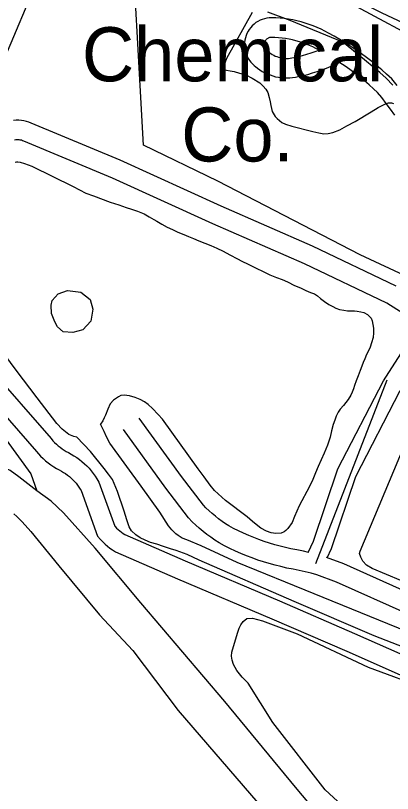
# Model space of a CAD drawing. Extents: x 3683613 to 3738215, y 469626 to 495384.
# Drawn here: x 3698541 to 3699120, y 478222 to 479415 of the extents above; entities that cross this region are included whole.
import ezdxf

# ---------------------------------------------------------------- set-up
doc = ezdxf.new("R2010")
doc.units = 0
for name, color, linetype in [('V-BLDG-IDEN', 7, 'Continuous'), ('V-ROAD-CNTR', 7, 'Continuous'), ('V-SITE-VEGE', 7, 'Continuous'), ('V-TOPO-SHOR', 7, 'Continuous')]:
    doc.layers.add(name, color=color, linetype=linetype)

msp = doc.modelspace()

# ---------------------------------------------------------------- linework, layer by layer
at = {"layer": 'V-ROAD-CNTR'}
for points in [[(3699021.9, 479388.6), (3699016.3, 479391.6), (3699010.5, 479394.5), (3699004.5, 479397.2), (3698998.4, 479399.6), (3698992.3, 479401.9), (3698986.1, 479403.9), (3698979.8, 479405.7), (3698973.4, 479407.3), (3698967, 479408.6), (3698960.6, 479409.8), (3698954.1, 479410.7), (3698947.6, 479411.3), (3698941.1, 479411.7), (3698934.3, 479411.9), (3698930.7, 479411.8), (3698927.2, 479411.3), (3698923.6, 479410.5), (3698920.2, 479409.5), (3698916.8, 479408.1), (3698913.6, 479406.4), (3698910.6, 479404.5), (3698907.7, 479402.2), (3698905, 479399.8), (3698902.6, 479397.1), (3698900.4, 479394.2), (3698898.4, 479391.2), (3698896.8, 479388), (3698895.4, 479384.6), (3698894.3, 479381.2), (3698893.5, 479377.6), (3698893.1, 479374), (3698892.9, 479370.4), (3698893.1, 479366.8), (3698893.6, 479363.2), (3698894.4, 479359.7), (3698895.5, 479356.2), (3698896.9, 479352.9), (3698898.5, 479349.7), (3698900.5, 479346.6), (3698902.7, 479343.8), (3698905.2, 479341.1), (3698907.8, 479338.7), (3698910.2, 479336.9)], [(3699127.4, 479308.1), (3699119.4, 479318.1), (3699111.3, 479325.5), (3699103.9, 479332.1), (3699096.2, 479338.5), (3699088.5, 479344.8), (3699080.6, 479350.9), (3699072.5, 479356.8), (3699064.4, 479362.5), (3699056.1, 479368.1), (3699047.7, 479373.5), (3699039.2, 479378.7), (3699030.6, 479383.7), (3699022.1, 479388.5)], [(3699007.6, 479362.2), (3699002.6, 479364.9), (3698997.7, 479367.3), (3698992.7, 479369.6), (3698987.6, 479371.6), (3698982.5, 479373.5), (3698977.3, 479375.2), (3698972, 479376.7), (3698966.7, 479378), (3698961.4, 479379.2), (3698956, 479380.1), (3698950.6, 479380.9), (3698945.1, 479381.4), (3698939.6, 479381.8), (3698934.5, 479381.9), (3698933.4, 479381.9), (3698932.4, 479381.8), (3698931.4, 479381.5), (3698930.4, 479381.2), (3698929.5, 479380.9), (3698928.6, 479380.4), (3698927.8, 479379.9), (3698927, 479379.3), (3698926.3, 479378.6), (3698925.6, 479377.8), (3698925, 479377.1), (3698924.5, 479376.2), (3698924, 479375.3), (3698923.6, 479374.4), (3698923.3, 479373.5), (3698923.1, 479372.5), (3698923, 479371.5), (3698922.9, 479370.5), (3698923, 479369.5), (3698923.1, 479368.5), (3698923.3, 479367.6), (3698923.6, 479366.6), (3698924, 479365.7), (3698924.5, 479364.8), (3698925, 479364), (3698925.6, 479363.2), (3698926.3, 479362.4), (3698927.1, 479361.8), (3698928.4, 479360.8)], [(3698928.7, 479360.5), (3698931.1, 479358.6), (3698933.2, 479357.1), (3698935.4, 479355.7), (3698937.8, 479354.5), (3698940.1, 479353.3), (3698942.6, 479352.4), (3698945.1, 479351.5), (3698947.6, 479350.8), (3698950.2, 479350.3), (3698952.8, 479349.9), (3698955.4, 479349.7), (3698958.1, 479349.6), (3698960.7, 479349.7), (3698963.3, 479350), (3698965.9, 479350.3), (3698968.8, 479351), (3698975.6, 479352.5), (3698982.2, 479354.2), (3698988.7, 479356), (3698995.2, 479358.1), (3699001.7, 479360.3), (3699007.3, 479362.4)], [(3698909.9, 479337.1), (3698913, 479334.7), (3698916.6, 479332.1), (3698920.3, 479329.8), (3698924.2, 479327.7), (3698928.2, 479325.8), (3698932.3, 479324.2), (3698936.4, 479322.8), (3698940.7, 479321.6), (3698945, 479320.7), (3698949.4, 479320.1), (3698953.7, 479319.7), (3698958.1, 479319.6), (3698962.5, 479319.8), (3698966.9, 479320.2), (3698971.3, 479320.8), (3698975.2, 479321.7), (3698982.6, 479323.3), (3698990, 479325.2), (3698997.3, 479327.3), (3699004.6, 479329.6), (3699011.9, 479332.1), (3699019, 479334.8), (3699026.1, 479337.7), (3699033.1, 479340.8), (3699038.9, 479343.5)], [(3699123.8, 479262.5), (3699117.3, 479271.7), (3699110.6, 479280.7), (3699103.8, 479289.6), (3699097.4, 479297.5), (3699091.3, 479303.2), (3699084.3, 479309.3), (3699077.1, 479315.3), (3699069.9, 479321.2), (3699062.5, 479326.9), (3699055, 479332.5), (3699047.4, 479337.8), (3699039.6, 479343), (3699038.9, 479343.5)], [(3699126.1, 479000.4), (3698997.4, 479061.5), (3698856.9, 479123), (3698702.2, 479193.5), (3698565.3, 479250.5), (3698562, 479251.8), (3698558.1, 479253), (3698554.2, 479253.9), (3698550.3, 479254.5), (3698546.3, 479254.8), (3698542.3, 479254.8), (3698538.3, 479254.5)], [(3699146.6, 478952), (3699111.6, 478974.1), (3698984.9, 479034.2), (3698844.6, 479095.6), (3698690.2, 479166), (3698554.1, 479222.7), (3698552.1, 479223.4), (3698550.4, 479224), (3698548.7, 479224.4), (3698546.9, 479224.6), (3698545.1, 479224.8), (3698543.4, 479224.8), (3698541.6, 479224.6), (3698539.8, 479224.4)], [(3698990.8, 478591.7), (3698998.7, 478608.7), (3699036.4, 478719.7), (3699106.3, 478854.9), (3699142.1, 478910.5)], [(3698500, 478876), (3698596.1, 478766.3), (3698598.8, 478763), (3698601.3, 478760.3), (3698604, 478757.7), (3698606.8, 478755.2), (3698609.7, 478752.9), (3698612.7, 478750.7), (3698615.8, 478748.6), (3698619, 478746.7), (3698622.6, 478744.8), (3698626.8, 478742.6), (3698631.1, 478740), (3698635.3, 478737.2), (3698639.4, 478734.3), (3698643.3, 478731.1), (3698647.1, 478727.8), (3698650.8, 478724.3), (3698654.2, 478720.7), (3698657.5, 478716.9), (3698660.6, 478712.9), (3698663.6, 478708.8), (3698666.3, 478704.6), (3698669.4, 478699.4), (3698693.8, 478632.1), (3698694.4, 478631.3), (3698696.6, 478628.9), (3698699, 478626.7), (3698701.5, 478624.6), (3698704.1, 478622.6), (3698706.7, 478620.7), (3698709, 478619.3), (3698801.8, 478578.6), (3698946.6, 478517.2), (3699061.9, 478467.4), (3699236, 478390.4)], [(3698476.5, 478857.4), (3698573.3, 478746.7), (3698576.4, 478743.1), (3698579.9, 478739.3), (3698583.6, 478735.7), (3698587.4, 478732.3), (3698591.4, 478729.1), (3698595.6, 478726), (3698599.9, 478723.2), (3698604.3, 478720.6), (3698608.5, 478718.3), (3698612.1, 478716.4), (3698615.2, 478714.5), (3698618.3, 478712.5), (3698621.2, 478710.4), (3698624.1, 478708.1), (3698626.8, 478705.7), (3698629.5, 478703.2), (3698632, 478700.5), (3698634.4, 478697.8), (3698636.6, 478694.9), (3698638.8, 478691.9), (3698640.8, 478688.8), (3698642.1, 478686.6), (3698667.4, 478616.8), (3698672, 478611.4), (3698675.3, 478607.8), (3698678.8, 478604.5), (3698682.5, 478601.3), (3698686.4, 478598.3), (3698690.4, 478595.6), (3698695, 478592.7), (3698789.9, 478551.1), (3698934.8, 478489.6), (3699049.9, 478439.9), (3699224, 478362.9)], [(3699002.7, 478574.6), (3699112.1, 478856.2)], [(3699020, 478583.3), (3699026.6, 478597.6), (3699064.1, 478707.9), (3699132.3, 478839.9)], [(3698991.2, 478591.6), (3698983.5, 478593.3), (3698973.6, 478595.4), (3698964.1, 478597.1), (3698955.9, 478599), (3698947.6, 478601), (3698939.4, 478603.3), (3698931.3, 478605.7), (3698923.2, 478608.4), (3698915.2, 478611.3), (3698907.2, 478614.3), (3698899.4, 478617.6), (3698891.6, 478621), (3698883.9, 478624.7), (3698876.3, 478628.5), (3698869.1, 478632.4), (3698863.9, 478635.7), (3698858.5, 478639.3), (3698853.3, 478643.1), (3698848.2, 478647.1), (3698843.3, 478651.2), (3698838.5, 478655.6), (3698833.8, 478660), (3698829.8, 478664.2), (3698796.3, 478708.3), (3698731.3, 478797.6)], [(3699254.6, 478447.6), (3699034.2, 478546.1), (3699004, 478557.2), (3698995.4, 478559.6), (3698986.2, 478561.9), (3698977.1, 478564), (3698967.8, 478565.9), (3698958.1, 478567.7), (3698949, 478569.8), (3698940, 478572), (3698931.1, 478574.5), (3698922.2, 478577.1), (3698913.4, 478580), (3698904.7, 478583.1), (3698896.1, 478586.5), (3698887.5, 478590), (3698879.1, 478593.8), (3698870.7, 478597.7), (3698862.4, 478601.9), (3698854, 478606.4), (3698847.4, 478610.6), (3698841.3, 478614.8), (3698835.2, 478619.2), (3698829.4, 478623.8), (3698823.6, 478628.6), (3698818.1, 478633.6), (3698812.7, 478638.7), (3698807, 478644.5), (3698772.2, 478690.4), (3698707.1, 478780)], [(3699592.3, 478326.1), (3699553.7, 478343.7), (3699535.4, 478352.6), (3699517.2, 478361.8), (3699499, 478371.1), (3699481, 478380.6), (3699462.5, 478390.6), (3699445.8, 478398.4), (3699429.3, 478405.8), (3699412.6, 478413.1), (3699395.9, 478420.1), (3699379.3, 478426.8), (3699266.6, 478475.1), (3699045.5, 478574), (3699018.9, 478583.7)]]:
    msp.add_lwpolyline(points, dxfattribs=at)
at = {"layer": 'V-SITE-VEGE'}
for points in [[(3699070.4, 478593.7), (3699138.2, 478754.7), (3699199.6, 478907.7), (3699221.2, 478955.3), (3699224.1, 478963.8), (3699224.6, 478968.1), (3699223.2, 478971.9), (3699220.1, 478976.2), (3699214.4, 478981), (3699070.8, 479048.5), (3698851.8, 479161.2), (3698737.7, 479216.5), (3698716.8, 479592.3), (3698909.3, 479507.2), (3699050.5, 479436.8), (3699184.3, 479365.6), (3699350.1, 479288.4), (3699481.2, 479225.7), (3699486.4, 479220.9), (3699489.7, 479217.1), (3699491.1, 479214.7), (3699491.7, 479212.8), (3699491.1, 479210.9)], [(3698905, 479419.9), (3698865.4, 479349.5), (3698859.3, 479332.6), (3698877.3, 479329.5), (3698885.5, 479327.2), (3698894.8, 479324.3), (3698904.6, 479319.3), (3698916.4, 479312.4), (3698921.9, 479307.3), (3698925.8, 479302.7), (3698928.6, 479297.3), (3698930.9, 479289.5), (3698932.3, 479283), (3698933.2, 479277.3), (3698935.5, 479268.3), (3698939.9, 479260.5), (3698943, 479257.3), (3698950.1, 479251.4), (3698956.1, 479248.5), (3698965.7, 479245.6), (3698997.9, 479237.6), (3699007.1, 479235.3), (3699015, 479234), (3699021.3, 479234.4), (3699028.6, 479236.1), (3699039.2, 479240), (3699050, 479246.4), (3699062.9, 479253.1), (3699087.7, 479267.9), (3699098.5, 479274.3), (3699108.5, 479279.5), (3699113.9, 479281.5), (3699118.8, 479281.3), (3699121.6, 479280.3)], [(3699120.6, 479308.8), (3699110.5, 479319.3), (3699100.6, 479327.8), (3699068.7, 479354.6), (3699043.9, 479374.4), (3698963, 479407.6), (3698928.6, 479420.8)], [(3698538.7, 478650.9), (3698543.4, 478646.9), (3698551.4, 478638.5), (3698564.9, 478623.8), (3698608, 478571), (3698670.1, 478496), (3698721.4, 478440.9), (3698791.1, 478349.1), (3698913.4, 478207.2)], [(3699198.9, 478520.8), (3699089.3, 478567), (3699080.2, 478572), (3699074.7, 478578.2), (3699071.4, 478584.1), (3699069.7, 478589.8), (3699070.4, 478593.7)], [(3699074, 478174.7), (3699016.7, 478227.3), (3698936.3, 478330.9), (3698898.5, 478391), (3698889.2, 478400.4), (3698881.1, 478410.7), (3698876.1, 478419.8), (3698874.1, 478426.1), (3698873, 478432.3), (3698873.7, 478438.8), (3698882.3, 478467.8), (3698884.9, 478475.4), (3698887.6, 478480.6), (3698891, 478485.6), (3698896.7, 478490), (3698905.1, 478490.6), (3698920.4, 478486.8), (3698973.7, 478466.5), (3699082.8, 478415.5), (3699174.6, 478381.6)]]:
    msp.add_lwpolyline(points, dxfattribs=at)
at = {"layer": 'V-TOPO-SHOR'}
for points in [[(3699092.8, 480674.9), (3699056.3, 480566.8), (3699000.1, 480429.1), (3698932, 480287.9), (3698883.2, 480164.2), (3698808.3, 479992.4), (3698727.5, 479798.8), (3698649.6, 479630), (3698592.1, 479510.8), (3698505.9, 479307.8), (3698454.9, 479190.3), (3698385.7, 479027.6), (3698377.7, 479009.8), (3698373.8, 478999.4), (3698370.9, 478989.3), (3698368.8, 478979.5), (3698369.8, 478971.9), (3698371.5, 478964), (3698374.3, 478957.2), (3698387.7, 478934.2), (3698461.9, 478844.2), (3698526.9, 478764.5), (3698564.6, 478712.1), (3698573.8, 478686.2)], [(3699842.3, 479071.9), (3699719, 479130.5), (3699543.3, 479210.5), (3699443, 479257.9), (3699268.4, 479342.6), (3699104.5, 479418.9), (3698979.2, 479481.8), (3698935.7, 479506), (3698883, 479528.2), (3698759.5, 479583.2), (3698649.6, 479630)], [(3698540.6, 479190.6), (3698542.8, 479191.1), (3698544.7, 479191.2), (3698548.5, 479190.4), (3698555.1, 479188.5), (3698566.2, 479184.3), (3698629.7, 479153), (3698649.3, 479143.1), (3698661.2, 479138.9)], [(3698661.2, 479138.9), (3698686.6, 479129.1), (3698700.1, 479125.1), (3698711.1, 479121.1), (3698719.6, 479118.2), (3698728.7, 479115.3), (3698738.7, 479111.1), (3698746.4, 479106.8), (3698753.6, 479102.5), (3698758.3, 479099.8), (3698765.8, 479095.2), (3698774.1, 479090.9), (3698782.6, 479086.9), (3698790.4, 479083.2), (3698799.8, 479079.2), (3698807.2, 479076.3), (3698814.9, 479073.1), (3698822.7, 479069.6), (3698832, 479066.4), (3698841.4, 479062.5), (3698850.5, 479058.7), (3698860.2, 479053.9), (3698870.4, 479048.3), (3698882.3, 479041.9), (3698888.9, 479038.4), (3698898.6, 479034.1), (3698910.8, 479027.9), (3698921.5, 479022.6), (3698931.8, 479017.5), (3698942.2, 479013.5), (3698950.8, 479010.4), (3698959.1, 479006.9), (3698969.6, 479001.3), (3698978.9, 478997.5), (3698987.2, 478993.5), (3698994.4, 478990.6), (3699000.5, 478988.2), (3699004.9, 478985.3), (3699009.6, 478981.5), (3699015.7, 478976.6), (3699022.6, 478972), (3699028.5, 478968.8), (3699033.4, 478966.4), (3699038.9, 478964.6), (3699045.3, 478963.3), (3699051, 478962.5), (3699056.3, 478962.3), (3699062, 478962.1), (3699065.9, 478961.9), (3699071.6, 478960.9), (3699076.3, 478959.6), (3699082.1, 478956.6), (3699085.2, 478953.6), (3699087.4, 478951.2), (3699088.8, 478947.1), (3699090.3, 478941.4), (3699091.2, 478935.9), (3699091.3, 478928.7), (3699090.6, 478921.3), (3699088.2, 478913.1), (3699085.8, 478906.7), (3699083.4, 478901.2), (3699080.5, 478895.1), (3699077.8, 478888.8), (3699075.1, 478883.2), (3699073, 478877.5), (3699070.4, 478870.6), (3699067.4, 478862.8), (3699064.5, 478854.8), (3699061.9, 478847.7), (3699060.3, 478842.7), (3699058.4, 478837.7), (3699056.3, 478832.8), (3699052.3, 478826.1), (3699045, 478817), (3699040.1, 478811.4), (3699036.9, 478806.7), (3699033.9, 478800.9), (3699031.5, 478794.8), (3699029.4, 478788), (3699026.8, 478778), (3699024.5, 478768.7), (3699020.5, 478756), (3699015.5, 478744.1), (3699010.7, 478733.6), (3699006.1, 478723.4), (3699001.9, 478713.8), (3698997.9, 478703.6), (3698992.8, 478692.8), (3698977, 478662.9), (3698973.3, 478654.7), (3698969.8, 478646.7), (3698966.1, 478637.5), (3698959.3, 478628.1), (3698956.6, 478625.3), (3698953.9, 478623.1), (3698949.5, 478621.4), (3698941.3, 478620.5), (3698933.9, 478621.8), (3698927, 478624.4), (3698918.2, 478629)], [(3698601.6, 478945.7), (3698596.7, 478958.3), (3698596, 478971), (3698597.5, 478978.4), (3698606.9, 478988.6), (3698621.1, 478993.5), (3698641.8, 478991.2), (3698656.2, 478979.7), (3698660.1, 478964.9), (3698657.2, 478946.4), (3698644.7, 478933), (3698629.4, 478929.1), (3698614.5, 478930), (3698606, 478937.8), (3698601.6, 478945.7)], [(3698635.5, 478768.3), (3698631.1, 478769.3), (3698623.4, 478772.8), (3698612.9, 478780.9), (3698604.8, 478789.6), (3698574.4, 478829), (3698542.5, 478871.4), (3698470.5, 478967.3)], [(3698546.4, 478707.8), (3698532.9, 478717.2), (3698521.6, 478722.5), (3698511.8, 478726.2), (3698478.7, 478739.9), (3698383.3, 478784.4), (3698262.3, 478827.8), (3698222.9, 478844.4)], [(3698918.2, 478629), (3698910.9, 478634.6), (3698905.4, 478639.2), (3698897.3, 478646), (3698863.8, 478671.3), (3698847.1, 478686.5), (3698840.4, 478694.9), (3698830.9, 478707.4), (3698821.7, 478719.7), (3698766.9, 478796.1), (3698760.3, 478803.4), (3698751.9, 478812.3), (3698745.2, 478818.8), (3698739.4, 478822.9), (3698732.5, 478826.1), (3698725.3, 478829.3), (3698716.2, 478831.9), (3698708.3, 478832.9), (3698703.1, 478832.3), (3698699.5, 478830.6), (3698691.6, 478825.3), (3698686.8, 478819.7), (3698683, 478811.4), (3698679.3, 478802.1), (3698677.7, 478798.2), (3698675.3, 478793.5), (3698671.8, 478788.2)], [(3699520.5, 478295.6), (3699520.9, 478301.5), (3699512.9, 478307.2), (3699480.1, 478323.7), (3699361.8, 478371.8), (3699317.3, 478393.2), (3699230.6, 478431.6), (3699157.2, 478464.1), (3698999.9, 478527.9), (3698881.5, 478576.1), (3698826.3, 478601.7), (3698804.2, 478611), (3698797, 478613.7), (3698790.9, 478617.4), (3698787.3, 478620.1), (3698781.2, 478626.1), (3698776.5, 478632.3), (3698762.8, 478653.6), (3698734.2, 478693.5), (3698686.4, 478759.3), (3698680.8, 478768.9), (3698677.2, 478777.1), (3698671.8, 478788.2)], [(3699255.4, 478400), (3699092.1, 478463.8), (3698969.3, 478516.3), (3698823.3, 478580), (3698804.8, 478588.2), (3698788, 478594.6), (3698779.1, 478597.2), (3698768.7, 478600.7), (3698758.5, 478604.1), (3698748.5, 478607), (3698740.5, 478610.2), (3698732.5, 478613.9), (3698725.9, 478618.5), (3698719.2, 478624.7), (3698715.6, 478631), (3698712.4, 478641.4), (3698708.1, 478654.8), (3698697.8, 478685.1), (3698690.5, 478703.4), (3698684.3, 478711.8), (3698677.3, 478720.5), (3698656.4, 478746.6), (3698635.5, 478768.3)], [(3698614.9, 478652.4), (3698596.2, 478670.3), (3698573.8, 478686.2), (3698546.4, 478707.8)], [(3699319.2, 477791.2), (3699304.6, 477834.7), (3699284.8, 477858.6), (3699157.6, 478013.1), (3699057.6, 478128.7), (3698971.4, 478231.4), (3698862.9, 478362.8), (3698733.6, 478514.3), (3698663.6, 478598.2), (3698614.9, 478652.4)]]:
    msp.add_lwpolyline(points, dxfattribs=at)

# ---------------------------------------------------------------- texts
at = {"layer": 'V-BLDG-IDEN'}
for s, p in [('Chemical', (3698643.3, 479314.5)), ('Co.', (3698795.7, 479191.5))]:
    msp.add_text(s, height=83, dxfattribs=at).set_placement(p)

doc.saveas('drawing.dxf')
